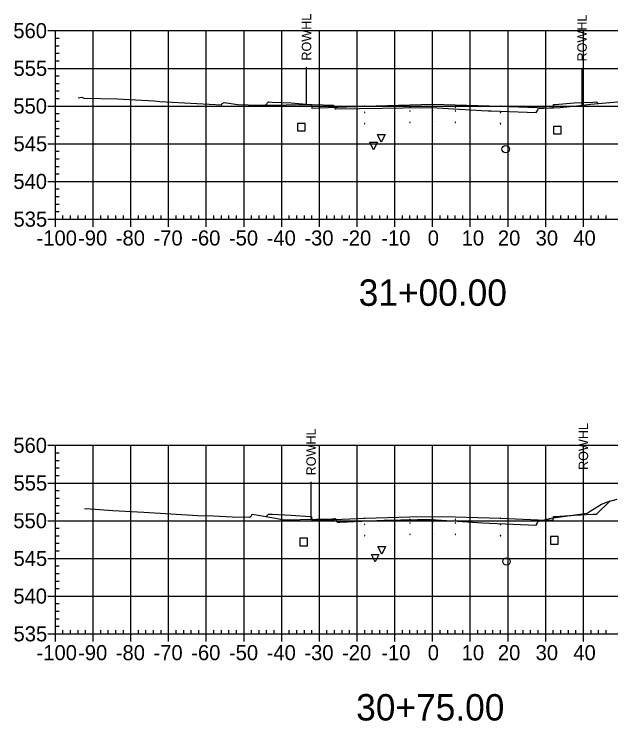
# Model space of a CAD drawing. Extents: x 708103 to 717568, y 374476 to 378707.
# Drawn here: x 710316 to 710474.2, y 377631.5 to 377819 of the extents above; entities that cross this region are included whole.
import ezdxf

# ---------------------------------------------------------------- set-up
doc = ezdxf.new("R2010")
doc.units = 0
for name, color, linetype in [('1', 7, 'Continuous'), ('10', 7, 'Continuous'), ('13', 7, 'Continuous'), ('14', 7, 'Continuous'), ('22', 7, 'Continuous'), ('4', 7, 'Continuous'), ('57', 7, 'Continuous'), ('Existing', 7, 'Continuous'), ('XS_Right_of_Way', 7, 'Continuous')]:
    doc.layers.add(name, color=color, linetype=linetype)

msp = doc.modelspace()

# ---------------------------------------------------------------- linework, layer by layer
for points in [[(710420.93, 377794.28), (710421.03, 377794.28), (710421.03, 377794.38), (710420.93, 377794.38)], [(710426.93, 377794.4), (710427.03, 377794.4), (710427.03, 377794.5), (710426.93, 377794.5)], [(710432.93, 377794.28), (710433.03, 377794.28), (710433.03, 377794.38), (710432.93, 377794.38)], [(710396.93, 377792.44), (710397.03, 377792.44), (710397.03, 377792.54), (710396.93, 377792.54)], [(710408.93, 377792.92), (710409.03, 377792.92), (710409.03, 377793.02), (710408.93, 377793.02)], [(710420.93, 377793.28), (710421.03, 377793.28), (710421.03, 377793.38), (710420.93, 377793.38)], [(710426.93, 377793.4), (710427.03, 377793.4), (710427.03, 377793.5), (710426.93, 377793.5)], [(710432.93, 377793.28), (710433.03, 377793.28), (710433.03, 377793.38), (710432.93, 377793.38)], [(710444.93, 377792.92), (710445.03, 377792.92), (710445.03, 377793.02), (710444.93, 377793.02)], [(710456.93, 377792.44), (710457.03, 377792.44), (710457.03, 377792.54), (710456.93, 377792.54)], [(710420.93, 377790.28), (710421.03, 377790.28), (710421.03, 377790.38), (710420.93, 377790.38)], [(710426.93, 377790.4), (710427.03, 377790.4), (710427.03, 377790.5), (710426.93, 377790.5)], [(710432.93, 377790.28), (710433.03, 377790.28), (710433.03, 377790.38), (710432.93, 377790.38)], [(710396.93, 377789.44), (710397.03, 377789.44), (710397.03, 377789.54), (710396.93, 377789.54)], [(710408.93, 377789.92), (710409.03, 377789.92), (710409.03, 377790.02), (710408.93, 377790.02)], [(710444.93, 377789.92), (710445.03, 377789.92), (710445.03, 377790.02), (710444.93, 377790.02)], [(710456.93, 377789.44), (710457.03, 377789.44), (710457.03, 377789.54), (710456.93, 377789.54)], [(710408.93, 377683.58), (710409.03, 377683.58), (710409.03, 377683.68), (710408.93, 377683.68)], [(710420.93, 377684.94), (710421.03, 377684.94), (710421.03, 377685.04), (710420.93, 377685.04)], [(710420.93, 377683.94), (710421.03, 377683.94), (710421.03, 377684.04), (710420.93, 377684.04)], [(710426.93, 377685.06), (710427.03, 377685.06), (710427.03, 377685.16), (710426.93, 377685.16)], [(710426.93, 377684.06), (710427.03, 377684.06), (710427.03, 377684.16), (710426.93, 377684.16)], [(710432.93, 377684.94), (710433.03, 377684.94), (710433.03, 377685.04), (710432.93, 377685.04)], [(710432.93, 377683.94), (710433.03, 377683.94), (710433.03, 377684.04), (710432.93, 377684.04)], [(710444.93, 377683.58), (710445.03, 377683.58), (710445.03, 377683.68), (710444.93, 377683.68)], [(710396.93, 377683.1), (710397.03, 377683.1), (710397.03, 377683.2), (710396.93, 377683.2)], [(710456.93, 377683.1), (710457.03, 377683.1), (710457.03, 377683.2), (710456.93, 377683.2)], [(710396.93, 377680.1), (710397.03, 377680.1), (710397.03, 377680.2), (710396.93, 377680.2)], [(710408.93, 377680.58), (710409.03, 377680.58), (710409.03, 377680.68), (710408.93, 377680.68)], [(710420.93, 377680.94), (710421.03, 377680.94), (710421.03, 377681.04), (710420.93, 377681.04)], [(710426.93, 377681.06), (710427.03, 377681.06), (710427.03, 377681.16), (710426.93, 377681.16)], [(710432.93, 377680.94), (710433.03, 377680.94), (710433.03, 377681.04), (710432.93, 377681.04)], [(710444.93, 377680.58), (710445.03, 377680.58), (710445.03, 377680.68), (710444.93, 377680.68)], [(710456.93, 377680.1), (710457.03, 377680.1), (710457.03, 377680.2), (710456.93, 377680.2)]]:
    msp.add_lwpolyline(points, close=True)
at = {"layer": '1'}
for points in [[(710413.38, 377785.07), (710412.38, 377787.07), (710414.38, 377787.07)], [(710411.35, 377783.03), (710410.35, 377785.03), (710412.35, 377785.03)], [(710413.49, 377675.77), (710412.49, 377677.77), (710414.49, 377677.77)], [(710411.74, 377673.69), (710410.74, 377675.69), (710412.74, 377675.69)]]:
    msp.add_lwpolyline(points, close=True, dxfattribs=at)
at = {"layer": '10'}
for points in [[(710391.19, 377788.03), (710393.19, 377788.03), (710393.19, 377790.03), (710391.19, 377790.03)], [(710391.79, 377678), (710393.79, 377678), (710393.79, 377680), (710391.79, 377680)]]:
    msp.add_lwpolyline(points, close=True, dxfattribs=at)
at = {"layer": '13'}
for centre in [(710446.38, 377783.19), (710446.57, 377673.81)]:
    msp.add_circle(centre, 1, dxfattribs=at)
at = {"layer": '14'}
for points in [[(710382.66, 377794.89), (710382.66, 377794.94), (710382.66, 377794.89), (710382.61, 377794.89), (710382.66, 377794.89), (710382.66, 377794.84), (710382.66, 377794.89), (710382.71, 377794.89)], [(710396.98, 377794.15), (710396.98, 377794.2), (710396.98, 377794.15), (710396.93, 377794.15), (710396.98, 377794.15), (710396.98, 377794.1), (710396.98, 377794.15), (710397.03, 377794.15)], [(710408.98, 377794.63), (710408.98, 377794.68), (710408.98, 377794.63), (710408.93, 377794.63), (710408.98, 377794.63), (710408.98, 377794.58), (710408.98, 377794.63), (710409.03, 377794.63)], [(710426.98, 377795.11), (710426.98, 377795.16), (710426.98, 377795.11), (710426.93, 377795.11), (710426.98, 377795.11), (710426.98, 377795.06), (710426.98, 377795.11), (710427.03, 377795.11)], [(710444.98, 377794.63), (710444.98, 377794.68), (710444.98, 377794.63), (710444.93, 377794.63), (710444.98, 377794.63), (710444.98, 377794.58), (710444.98, 377794.63), (710445.03, 377794.63)], [(710456.98, 377794.15), (710456.98, 377794.2), (710456.98, 377794.15), (710456.93, 377794.15), (710456.98, 377794.15), (710456.98, 377794.1), (710456.98, 377794.15), (710457.03, 377794.15)], [(710470.92, 377795.27), (710470.92, 377795.32), (710470.92, 377795.27), (710470.87, 377795.27), (710470.92, 377795.27), (710470.92, 377795.22), (710470.92, 377795.27), (710470.97, 377795.27)], [(710473.93, 377689.82), (710473.93, 377689.87), (710473.93, 377689.82), (710473.88, 377689.82), (710473.93, 377689.82), (710473.93, 377689.77), (710473.93, 377689.82), (710473.98, 377689.82)], [(710382.84, 377685.72), (710382.84, 377685.77), (710382.84, 377685.72), (710382.79, 377685.72), (710382.84, 377685.72), (710382.84, 377685.67), (710382.84, 377685.72), (710382.89, 377685.72)], [(710426.98, 377685.77), (710426.98, 377685.82), (710426.98, 377685.77), (710426.93, 377685.77), (710426.98, 377685.77), (710426.98, 377685.72), (710426.98, 377685.77), (710427.03, 377685.77)], [(710396.98, 377684.81), (710396.98, 377684.86), (710396.98, 377684.81), (710396.93, 377684.81), (710396.98, 377684.81), (710396.98, 377684.76), (710396.98, 377684.81), (710397.03, 377684.81)], [(710408.98, 377685.29), (710408.98, 377685.34), (710408.98, 377685.29), (710408.93, 377685.29), (710408.98, 377685.29), (710408.98, 377685.24), (710408.98, 377685.29), (710409.03, 377685.29)], [(710444.98, 377685.29), (710444.98, 377685.34), (710444.98, 377685.29), (710444.93, 377685.29), (710444.98, 377685.29), (710444.98, 377685.24), (710444.98, 377685.29), (710445.03, 377685.29)], [(710456.98, 377684.81), (710456.98, 377684.86), (710456.98, 377684.81), (710456.93, 377684.81), (710456.98, 377684.81), (710456.98, 377684.76), (710456.98, 377684.81), (710457.03, 377684.81)]]:
    msp.add_lwpolyline(points, dxfattribs=at)
at = {"layer": '22'}
for points in [[(710382.66, 377794.89), (710383.48, 377795.71), (710384.48, 377795.67), (710389.48, 377795.47), (710394.48, 377795.07), (710394.9, 377795.07), (710394.98, 377794.07), (710396.98, 377794.15), (710408.98, 377794.63), (710420.98, 377794.99), (710426.98, 377795.11), (710432.98, 377794.99), (710444.98, 377794.63), (710456.98, 377794.15), (710458.98, 377794.07), (710459.07, 377795.07), (710459.48, 377795.07), (710464.48, 377795.47), (710469.48, 377795.67), (710470.48, 377795.71), (710470.92, 377795.27)], [(710382.84, 377685.72), (710383.48, 377686.37), (710384.48, 377686.33), (710389.48, 377686.13), (710394.48, 377685.73), (710394.9, 377685.73), (710394.98, 377684.73), (710396.98, 377684.81), (710408.98, 377685.29), (710420.98, 377685.65), (710426.98, 377685.77), (710432.98, 377685.65), (710444.98, 377685.29), (710456.98, 377684.81), (710458.98, 377684.73), (710459.07, 377685.73), (710459.48, 377685.73), (710464.48, 377686.13), (710469.48, 377686.33), (710470.48, 377686.37), (710473.93, 377689.82)]]:
    msp.add_lwpolyline(points, dxfattribs=at)
at = {"layer": '4'}
for points in [[(710459.08, 377787.24), (710461.08, 377787.24), (710461.08, 377789.24), (710459.08, 377789.24)], [(710458.23, 377678.42), (710460.23, 377678.42), (710460.23, 377680.42), (710458.23, 377680.42)]]:
    msp.add_lwpolyline(points, close=True, dxfattribs=at)
at = {"layer": '57'}
for p, q in [((710324.98, 377814.63), (710326.98, 377814.63)), ((710326.98, 377814.63), (710526.98, 377814.63)), ((710326.98, 377764.63), (710326.98, 377814.63)), ((710326.98, 377764.63), (710326.98, 377814.63)), ((710336.98, 377764.63), (710336.98, 377814.63)), ((710346.98, 377764.63), (710346.98, 377814.63)), ((710356.98, 377764.63), (710356.98, 377814.63)), ((710366.98, 377764.63), (710366.98, 377814.63)), ((710376.98, 377764.63), (710376.98, 377814.63)), ((710386.98, 377764.63), (710386.98, 377814.63)), ((710396.98, 377764.63), (710396.98, 377814.63)), ((710406.98, 377764.63), (710406.98, 377814.63)), ((710416.98, 377764.63), (710416.98, 377814.63)), ((710426.98, 377764.63), (710426.98, 377814.63)), ((710436.98, 377764.63), (710436.98, 377814.63)), ((710446.98, 377764.63), (710446.98, 377814.63)), ((710456.98, 377764.63), (710456.98, 377814.63)), ((710466.98, 377764.63), (710466.98, 377814.63)), ((710326.98, 377812.63), (710327.98, 377812.63)), ((710326.98, 377810.63), (710327.98, 377810.63)), ((710326.98, 377808.63), (710327.98, 377808.63)), ((710326.98, 377806.63), (710327.98, 377806.63)), ((710324.98, 377804.63), (710326.98, 377804.63)), ((710326.98, 377804.63), (710526.98, 377804.63)), ((710326.98, 377802.63), (710327.98, 377802.63)), ((710326.98, 377800.63), (710327.98, 377800.63)), ((710326.98, 377798.63), (710327.98, 377798.63)), ((710326.98, 377796.63), (710327.98, 377796.63)), ((710324.98, 377794.63), (710326.98, 377794.63)), ((710326.98, 377794.63), (710526.98, 377794.63)), ((710326.98, 377792.63), (710327.98, 377792.63)), ((710326.98, 377790.63), (710327.98, 377790.63)), ((710326.98, 377788.63), (710327.98, 377788.63)), ((710326.98, 377786.63), (710327.98, 377786.63)), ((710324.98, 377784.63), (710326.98, 377784.63)), ((710326.98, 377784.63), (710526.98, 377784.63)), ((710326.98, 377782.63), (710327.98, 377782.63)), ((710326.98, 377780.63), (710327.98, 377780.63)), ((710326.98, 377778.63), (710327.98, 377778.63)), ((710326.98, 377776.63), (710327.98, 377776.63)), ((710324.98, 377774.63), (710326.98, 377774.63)), ((710326.98, 377774.63), (710526.98, 377774.63)), ((710326.98, 377772.63), (710327.98, 377772.63)), ((710326.98, 377770.63), (710327.98, 377770.63)), ((710326.98, 377768.63), (710327.98, 377768.63)), ((710326.98, 377766.63), (710327.98, 377766.63)), ((710324.98, 377764.63), (710326.98, 377764.63)), ((710326.98, 377764.63), (710526.98, 377764.63)), ((710326.98, 377764.63), (710526.98, 377764.63)), ((710326.98, 377762.63), (710326.98, 377764.63)), ((710328.98, 377764.63), (710328.98, 377765.63)), ((710330.98, 377764.63), (710330.98, 377765.63)), ((710332.98, 377764.63), (710332.98, 377765.63)), ((710334.98, 377764.63), (710334.98, 377765.63)), ((710336.98, 377762.63), (710336.98, 377764.63)), ((710338.98, 377764.63), (710338.98, 377765.63)), ((710340.98, 377764.63), (710340.98, 377765.63)), ((710342.98, 377764.63), (710342.98, 377765.63)), ((710344.98, 377764.63), (710344.98, 377765.63)), ((710346.98, 377762.63), (710346.98, 377764.63)), ((710348.98, 377764.63), (710348.98, 377765.63)), ((710350.98, 377764.63), (710350.98, 377765.63)), ((710352.98, 377764.63), (710352.98, 377765.63)), ((710354.98, 377764.63), (710354.98, 377765.63)), ((710356.98, 377762.63), (710356.98, 377764.63)), ((710358.98, 377764.63), (710358.98, 377765.63)), ((710360.98, 377764.63), (710360.98, 377765.63)), ((710362.98, 377764.63), (710362.98, 377765.63)), ((710364.98, 377764.63), (710364.98, 377765.63)), ((710366.98, 377762.63), (710366.98, 377764.63)), ((710368.98, 377764.63), (710368.98, 377765.63)), ((710370.98, 377764.63), (710370.98, 377765.63)), ((710372.98, 377764.63), (710372.98, 377765.63)), ((710374.98, 377764.63), (710374.98, 377765.63)), ((710376.98, 377762.63), (710376.98, 377764.63)), ((710378.98, 377764.63), (710378.98, 377765.63)), ((710380.98, 377764.63), (710380.98, 377765.63)), ((710382.98, 377764.63), (710382.98, 377765.63)), ((710384.98, 377764.63), (710384.98, 377765.63)), ((710386.98, 377762.63), (710386.98, 377764.63)), ((710388.98, 377764.63), (710388.98, 377765.63)), ((710390.98, 377764.63), (710390.98, 377765.63)), ((710392.98, 377764.63), (710392.98, 377765.63)), ((710394.98, 377764.63), (710394.98, 377765.63)), ((710396.98, 377762.63), (710396.98, 377764.63)), ((710398.98, 377764.63), (710398.98, 377765.63)), ((710400.98, 377764.63), (710400.98, 377765.63)), ((710402.98, 377764.63), (710402.98, 377765.63)), ((710404.98, 377764.63), (710404.98, 377765.63)), ((710406.98, 377762.63), (710406.98, 377764.63)), ((710408.98, 377764.63), (710408.98, 377765.63)), ((710410.98, 377764.63), (710410.98, 377765.63)), ((710412.98, 377764.63), (710412.98, 377765.63)), ((710414.98, 377764.63), (710414.98, 377765.63)), ((710416.98, 377762.63), (710416.98, 377764.63)), ((710418.98, 377764.63), (710418.98, 377765.63)), ((710420.98, 377764.63), (710420.98, 377765.63)), ((710422.98, 377764.63), (710422.98, 377765.63)), ((710424.98, 377764.63), (710424.98, 377765.63)), ((710426.98, 377762.63), (710426.98, 377764.63)), ((710428.98, 377764.63), (710428.98, 377765.63)), ((710430.98, 377764.63), (710430.98, 377765.63)), ((710432.98, 377764.63), (710432.98, 377765.63)), ((710434.98, 377764.63), (710434.98, 377765.63)), ((710436.98, 377762.63), (710436.98, 377764.63)), ((710438.98, 377764.63), (710438.98, 377765.63)), ((710440.98, 377764.63), (710440.98, 377765.63)), ((710442.98, 377764.63), (710442.98, 377765.63)), ((710444.98, 377764.63), (710444.98, 377765.63)), ((710446.98, 377762.63), (710446.98, 377764.63)), ((710448.98, 377764.63), (710448.98, 377765.63)), ((710450.98, 377764.63), (710450.98, 377765.63)), ((710452.98, 377764.63), (710452.98, 377765.63)), ((710454.98, 377764.63), (710454.98, 377765.63)), ((710456.98, 377762.63), (710456.98, 377764.63)), ((710458.98, 377764.63), (710458.98, 377765.63)), ((710460.98, 377764.63), (710460.98, 377765.63)), ((710462.98, 377764.63), (710462.98, 377765.63)), ((710464.98, 377764.63), (710464.98, 377765.63)), ((710466.98, 377762.63), (710466.98, 377764.63)), ((710468.98, 377764.63), (710468.98, 377765.63)), ((710470.98, 377764.63), (710470.98, 377765.63)), ((710472.98, 377764.63), (710472.98, 377765.63)), ((710324.98, 377704.63), (710326.98, 377704.63)), ((710326.98, 377704.63), (710526.98, 377704.63)), ((710326.98, 377654.63), (710326.98, 377704.63)), ((710326.98, 377654.63), (710326.98, 377704.63)), ((710336.98, 377654.63), (710336.98, 377704.63)), ((710346.98, 377654.63), (710346.98, 377704.63)), ((710356.98, 377654.63), (710356.98, 377704.63)), ((710366.98, 377654.63), (710366.98, 377704.63)), ((710376.98, 377654.63), (710376.98, 377704.63)), ((710386.98, 377654.63), (710386.98, 377704.63)), ((710396.98, 377654.63), (710396.98, 377704.63)), ((710406.98, 377654.63), (710406.98, 377704.63)), ((710416.98, 377654.63), (710416.98, 377704.63)), ((710426.98, 377654.63), (710426.98, 377704.63)), ((710436.98, 377654.63), (710436.98, 377704.63)), ((710446.98, 377654.63), (710446.98, 377704.63)), ((710456.98, 377654.63), (710456.98, 377704.63)), ((710466.98, 377654.63), (710466.98, 377704.63)), ((710326.98, 377702.63), (710327.98, 377702.63)), ((710326.98, 377700.63), (710327.98, 377700.63)), ((710326.98, 377698.63), (710327.98, 377698.63)), ((710326.98, 377696.63), (710327.98, 377696.63)), ((710324.98, 377694.63), (710326.98, 377694.63)), ((710326.98, 377694.63), (710526.98, 377694.63)), ((710326.98, 377692.63), (710327.98, 377692.63)), ((710326.98, 377690.63), (710327.98, 377690.63)), ((710326.98, 377688.63), (710327.98, 377688.63)), ((710326.98, 377686.63), (710327.98, 377686.63)), ((710324.98, 377684.63), (710326.98, 377684.63)), ((710326.98, 377684.63), (710526.98, 377684.63)), ((710326.98, 377682.63), (710327.98, 377682.63)), ((710326.98, 377680.63), (710327.98, 377680.63)), ((710326.98, 377678.63), (710327.98, 377678.63)), ((710326.98, 377676.63), (710327.98, 377676.63)), ((710324.98, 377674.63), (710326.98, 377674.63)), ((710326.98, 377674.63), (710526.98, 377674.63)), ((710326.98, 377672.63), (710327.98, 377672.63)), ((710326.98, 377670.63), (710327.98, 377670.63)), ((710326.98, 377668.63), (710327.98, 377668.63)), ((710326.98, 377666.63), (710327.98, 377666.63)), ((710324.98, 377664.63), (710326.98, 377664.63)), ((710326.98, 377664.63), (710526.98, 377664.63)), ((710326.98, 377662.63), (710327.98, 377662.63)), ((710326.98, 377660.63), (710327.98, 377660.63)), ((710326.98, 377658.63), (710327.98, 377658.63)), ((710326.98, 377656.63), (710327.98, 377656.63)), ((710328.98, 377654.63), (710328.98, 377655.63)), ((710330.98, 377654.63), (710330.98, 377655.63)), ((710332.98, 377654.63), (710332.98, 377655.63)), ((710334.98, 377654.63), (710334.98, 377655.63)), ((710338.98, 377654.63), (710338.98, 377655.63)), ((710340.98, 377654.63), (710340.98, 377655.63)), ((710342.98, 377654.63), (710342.98, 377655.63)), ((710344.98, 377654.63), (710344.98, 377655.63)), ((710348.98, 377654.63), (710348.98, 377655.63)), ((710350.98, 377654.63), (710350.98, 377655.63)), ((710352.98, 377654.63), (710352.98, 377655.63)), ((710354.98, 377654.63), (710354.98, 377655.63)), ((710358.98, 377654.63), (710358.98, 377655.63)), ((710360.98, 377654.63), (710360.98, 377655.63)), ((710362.98, 377654.63), (710362.98, 377655.63)), ((710364.98, 377654.63), (710364.98, 377655.63)), ((710368.98, 377654.63), (710368.98, 377655.63)), ((710370.98, 377654.63), (710370.98, 377655.63)), ((710372.98, 377654.63), (710372.98, 377655.63)), ((710374.98, 377654.63), (710374.98, 377655.63)), ((710378.98, 377654.63), (710378.98, 377655.63)), ((710380.98, 377654.63), (710380.98, 377655.63)), ((710382.98, 377654.63), (710382.98, 377655.63)), ((710384.98, 377654.63), (710384.98, 377655.63)), ((710388.98, 377654.63), (710388.98, 377655.63)), ((710390.98, 377654.63), (710390.98, 377655.63)), ((710392.98, 377654.63), (710392.98, 377655.63)), ((710394.98, 377654.63), (710394.98, 377655.63)), ((710398.98, 377654.63), (710398.98, 377655.63)), ((710400.98, 377654.63), (710400.98, 377655.63)), ((710402.98, 377654.63), (710402.98, 377655.63)), ((710404.98, 377654.63), (710404.98, 377655.63)), ((710408.98, 377654.63), (710408.98, 377655.63)), ((710410.98, 377654.63), (710410.98, 377655.63)), ((710412.98, 377654.63), (710412.98, 377655.63)), ((710414.98, 377654.63), (710414.98, 377655.63)), ((710418.98, 377654.63), (710418.98, 377655.63)), ((710420.98, 377654.63), (710420.98, 377655.63)), ((710422.98, 377654.63), (710422.98, 377655.63)), ((710424.98, 377654.63), (710424.98, 377655.63)), ((710428.98, 377654.63), (710428.98, 377655.63)), ((710430.98, 377654.63), (710430.98, 377655.63)), ((710432.98, 377654.63), (710432.98, 377655.63)), ((710434.98, 377654.63), (710434.98, 377655.63)), ((710438.98, 377654.63), (710438.98, 377655.63)), ((710440.98, 377654.63), (710440.98, 377655.63)), ((710442.98, 377654.63), (710442.98, 377655.63)), ((710444.98, 377654.63), (710444.98, 377655.63)), ((710448.98, 377654.63), (710448.98, 377655.63)), ((710450.98, 377654.63), (710450.98, 377655.63)), ((710452.98, 377654.63), (710452.98, 377655.63)), ((710454.98, 377654.63), (710454.98, 377655.63)), ((710458.98, 377654.63), (710458.98, 377655.63)), ((710460.98, 377654.63), (710460.98, 377655.63)), ((710462.98, 377654.63), (710462.98, 377655.63)), ((710464.98, 377654.63), (710464.98, 377655.63)), ((710468.98, 377654.63), (710468.98, 377655.63)), ((710470.98, 377654.63), (710470.98, 377655.63)), ((710472.98, 377654.63), (710472.98, 377655.63)), ((710324.98, 377654.63), (710326.98, 377654.63)), ((710326.98, 377654.63), (710526.98, 377654.63)), ((710326.98, 377654.63), (710526.98, 377654.63)), ((710326.98, 377652.63), (710326.98, 377654.63)), ((710336.98, 377652.63), (710336.98, 377654.63)), ((710346.98, 377652.63), (710346.98, 377654.63)), ((710356.98, 377652.63), (710356.98, 377654.63)), ((710366.98, 377652.63), (710366.98, 377654.63)), ((710376.98, 377652.63), (710376.98, 377654.63)), ((710386.98, 377652.63), (710386.98, 377654.63)), ((710396.98, 377652.63), (710396.98, 377654.63)), ((710406.98, 377652.63), (710406.98, 377654.63)), ((710416.98, 377652.63), (710416.98, 377654.63)), ((710426.98, 377652.63), (710426.98, 377654.63)), ((710436.98, 377652.63), (710436.98, 377654.63)), ((710446.98, 377652.63), (710446.98, 377654.63)), ((710456.98, 377652.63), (710456.98, 377654.63)), ((710466.98, 377652.63), (710466.98, 377654.63))]:
    msp.add_line(p, q, dxfattribs=at)
at = {"layer": 'Existing'}
for points in [[(710333.03, 377796.84), (710334, 377797.01), (710334.47, 377796.71), (710343.45, 377796.52), (710353.19, 377795.98), (710354.66, 377795.85), (710370.99, 377794.91), (710371.07, 377795.22), (710371.72, 377795.61), (710375.37, 377795.04), (710380.8, 377794.86), (710395.52, 377795.08), (710400.53, 377794.86), (710400.68, 377794.83), (710401.13, 377793.88), (710401.13, 377793.87), (710401.32, 377793.88), (710413.72, 377794.07), (710419.17, 377794.11), (710426.69, 377794.24), (710438.6, 377793.54), (710439.93, 377793.46), (710441.73, 377793.35), (710442.07, 377793.35), (710442.55, 377793.33), (710454.48, 377792.89), (710454.77, 377793.48), (710455.03, 377793.98), (710458.01, 377794.15), (710460.8, 377794.27), (710466, 377794.76), (710467.4, 377794.93), (710468.89, 377795.09), (710478.02, 377795.9)], [(710334.66, 377687.75), (710335.11, 377687.83), (710342.16, 377687.38), (710350.4, 377686.86), (710364.77, 377686.04), (710368.8, 377685.89), (710373.87, 377685.64), (710378.41, 377685.57), (710378.89, 377685.86), (710379.12, 377686.34), (710384.39, 377685.47), (710387.6, 377684.9), (710400.39, 377685.14), (710401.1, 377685.21), (710401.22, 377685.18), (710401.23, 377685.15), (710401.67, 377684.21), (710402.36, 377684.23), (710414.16, 377684.81), (710422.98, 377684.91), (710426.61, 377684.98), (710437.6, 377684.26), (710440.23, 377684.11), (710442.1, 377683.99), (710454.42, 377683.49), (710454.68, 377683.91), (710454.91, 377684.42), (710457.96, 377685.19), (710459.37, 377685.44), (710459.66, 377685.48), (710460.23, 377685.56), (710461.62, 377685.75), (710467.94, 377686.61), (710468.8, 377687.15), (710471.72, 377689.04), (710473.32, 377689.65), (710475.9, 377690.37)]]:
    msp.add_lwpolyline(points, dxfattribs=at)
at = {"layer": 'XS_Right_of_Way'}
for p, q in [((710393.47, 377804.92), (710393.47, 377794.92)), ((710466.53, 377804.68), (710466.53, 377794.68)), ((710394.69, 377694.9), (710394.69, 377684.9)), ((710466.89, 377696.33), (710466.89, 377686.33))]:
    msp.add_line(p, q, dxfattribs=at)

# ---------------------------------------------------------------- texts
at = {"layer": '1'}
for s, p in [('31+00.00', (710407.39, 377741.63)), ('30+75.00', (710406.71, 377631.63))]:
    msp.add_text(s, height=7, dxfattribs=at).set_placement(p)
at = {"layer": '14'}
for p in [(710384.45, 377795.62), (710384.45, 377794.96), (710389.45, 377794.76), (710464.45, 377794.76), (710469.45, 377795.62), (710469.45, 377794.96), (710384.45, 377686.28), (710384.45, 377685.62), (710389.45, 377685.42), (710464.45, 377685.42), (710469.45, 377686.28), (710469.45, 377685.62)]:
    msp.add_text('+', height=0.1, dxfattribs=at).set_placement(p)
at = {"layer": '57'}
for s, p in [('560', (710315.81, 377812.63)), ('555', (710315.86, 377802.63)), ('550', (710315.81, 377792.63)), ('545', (710315.86, 377782.63)), ('540', (710315.81, 377772.63)), ('535', (710315.86, 377762.63)), ('-100', (710321.97, 377757.63)), ('-90', (710332.98, 377757.63)), ('-80', (710342.98, 377757.63)), ('-70', (710352.98, 377757.63)), ('-60', (710362.98, 377757.63)), ('-50', (710372.98, 377757.63)), ('-40', (710382.98, 377757.63)), ('-30', (710392.98, 377757.63)), ('-20', (710402.98, 377757.63)), ('-10', (710413.37, 377757.63)), ('0', (710425.69, 377757.63)), ('10', (710434.68, 377757.63)), ('20', (710444.29, 377757.63)), ('30', (710454.29, 377757.63)), ('40', (710464.29, 377757.63)), ('560', (710315.81, 377702.63)), ('555', (710315.86, 377692.63)), ('550', (710315.81, 377682.63)), ('545', (710315.86, 377672.63)), ('540', (710315.81, 377662.63)), ('535', (710315.86, 377652.63)), ('-100', (710321.97, 377647.63)), ('-90', (710332.98, 377647.63)), ('-80', (710342.98, 377647.63)), ('-70', (710352.98, 377647.63)), ('-60', (710362.98, 377647.63)), ('-50', (710372.98, 377647.63)), ('-40', (710382.98, 377647.63)), ('-30', (710392.98, 377647.63)), ('-20', (710402.98, 377647.63)), ('-10', (710413.37, 377647.63)), ('0', (710425.69, 377647.63)), ('10', (710434.68, 377647.63)), ('20', (710444.29, 377647.63)), ('30', (710454.29, 377647.63)), ('40', (710464.29, 377647.63))]:
    msp.add_text(s, height=4, dxfattribs=at).set_placement(p)
at = {"layer": 'XS_Right_of_Way'}
for p in [(710394.79, 377806.68), (710467.85, 377806.45), (710468.21, 377698.09), (710396.01, 377696.66)]:
    msp.add_text('ROWHL', height=2.5, rotation=90, dxfattribs=at).set_placement(p)

doc.saveas('drawing.dxf')
